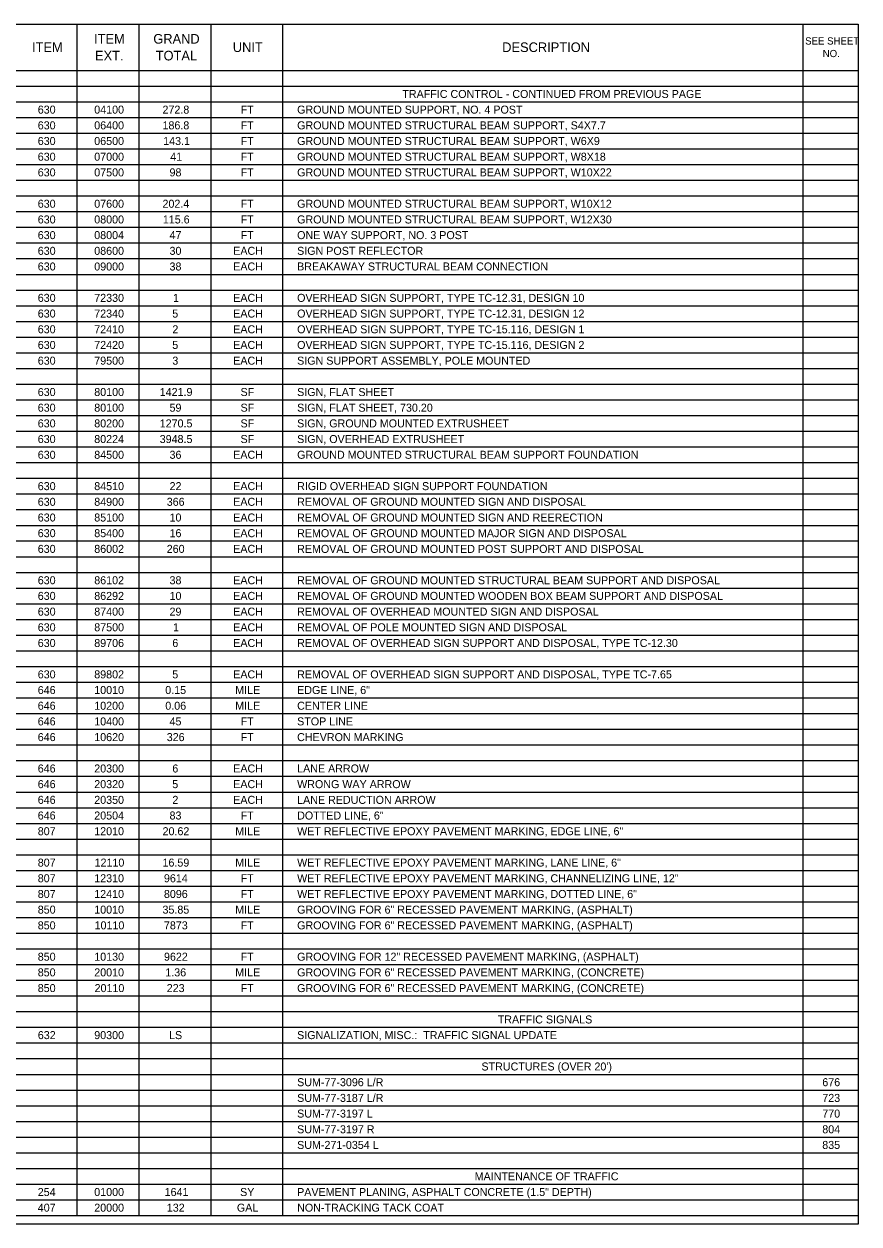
# Model space of a CAD drawing. Extents: x -542 to 295, y -281 to 32.
# Drawn here: x -400.45 to -385.84, y -130.59 to -109.59 of the extents above; entities that cross this region are included whole.
import ezdxf

# ---------------------------------------------------------------- set-up
doc = ezdxf.new("R2010")
doc.units = 0
for name, color, linetype in [('SC_Scratch1', 7, 'Continuous'), ('SH_Data', 7, 'Continuous'), ('SH_Text', 7, 'Continuous')]:
    doc.layers.add(name, color=color, linetype=linetype)

msp = doc.modelspace()

# ---------------------------------------------------------------- linework, layer by layer
at = {"layer": 'SC_Scratch1'}
msp.add_lwpolyline([(-416.359, -109.593), (-385.859, -109.593), (-385.859, -130.593), (-416.359, -130.593)], close=True, dxfattribs=at)
at = {"layer": 'SH_Data'}
for p, q in [((-416.359, -109.593), (-385.859, -109.593)), ((-399.523, -109.593), (-399.523, -130.444)), ((-398.437, -109.593), (-398.437, -130.444)), ((-397.182, -109.593), (-397.182, -130.444)), ((-395.926, -109.593), (-395.926, -130.444)), ((-386.827, -109.593), (-386.827, -130.444)), ((-385.859, -109.593), (-385.859, -130.444)), ((-416.359, -110.405), (-385.859, -110.405)), ((-416.359, -110.68), (-385.859, -110.68)), ((-416.359, -110.68), (-385.859, -110.68)), ((-416.359, -110.954), (-385.859, -110.954)), ((-416.359, -111.229), (-385.859, -111.229)), ((-416.359, -111.503), (-385.859, -111.503)), ((-416.359, -111.778), (-385.859, -111.778)), ((-416.359, -112.052), (-385.859, -112.052)), ((-416.359, -112.327), (-385.859, -112.327)), ((-416.359, -112.601), (-385.859, -112.601)), ((-416.359, -112.876), (-385.859, -112.876)), ((-416.359, -113.15), (-385.859, -113.15)), ((-416.359, -113.425), (-385.859, -113.425)), ((-416.359, -113.699), (-385.859, -113.699)), ((-416.359, -113.974), (-385.859, -113.974)), ((-416.359, -114.248), (-385.859, -114.248)), ((-416.359, -114.523), (-385.859, -114.523)), ((-416.359, -114.797), (-385.859, -114.797)), ((-416.359, -115.072), (-385.859, -115.072)), ((-416.359, -115.346), (-385.859, -115.346)), ((-416.359, -115.621), (-385.859, -115.621)), ((-416.359, -115.895), (-385.859, -115.895)), ((-416.359, -116.17), (-385.859, -116.17)), ((-416.359, -116.444), (-385.859, -116.444)), ((-416.359, -116.719), (-385.859, -116.719)), ((-416.359, -116.993), (-385.859, -116.993)), ((-416.359, -117.268), (-385.859, -117.268)), ((-416.359, -117.542), (-385.859, -117.542)), ((-416.359, -117.817), (-385.859, -117.817)), ((-416.359, -118.091), (-385.859, -118.091)), ((-416.359, -118.366), (-385.859, -118.366)), ((-416.359, -118.64), (-385.859, -118.64)), ((-416.359, -118.915), (-385.859, -118.915)), ((-416.359, -119.189), (-385.859, -119.189)), ((-416.359, -119.464), (-385.859, -119.464)), ((-416.359, -119.738), (-385.859, -119.738)), ((-416.359, -120.013), (-385.859, -120.013)), ((-416.359, -120.287), (-385.859, -120.287)), ((-416.359, -120.562), (-385.859, -120.562)), ((-416.359, -120.836), (-385.859, -120.836)), ((-416.359, -121.111), (-385.859, -121.111)), ((-416.359, -121.385), (-385.859, -121.385)), ((-416.359, -121.66), (-385.859, -121.66)), ((-416.359, -121.935), (-385.859, -121.935)), ((-416.359, -122.209), (-385.859, -122.209)), ((-416.359, -122.484), (-385.859, -122.484)), ((-416.359, -122.758), (-385.859, -122.758)), ((-416.359, -123.033), (-385.859, -123.033)), ((-416.359, -123.307), (-385.859, -123.307)), ((-416.359, -123.582), (-385.859, -123.582)), ((-416.359, -123.856), (-385.859, -123.856)), ((-416.359, -124.131), (-385.859, -124.131)), ((-416.359, -124.405), (-385.859, -124.405)), ((-416.359, -124.68), (-385.859, -124.68)), ((-416.359, -124.954), (-385.859, -124.954)), ((-416.359, -125.229), (-385.859, -125.229)), ((-416.359, -125.229), (-385.859, -125.229)), ((-416.359, -125.503), (-385.859, -125.503)), ((-416.359, -125.778), (-385.859, -125.778)), ((-416.359, -126.052), (-385.859, -126.052)), ((-416.359, -126.327), (-385.859, -126.327)), ((-416.359, -126.601), (-385.859, -126.601)), ((-416.359, -126.876), (-385.859, -126.876)), ((-416.359, -127.15), (-385.859, -127.15)), ((-416.359, -127.425), (-385.859, -127.425)), ((-416.359, -127.699), (-385.859, -127.699)), ((-416.359, -127.974), (-385.859, -127.974)), ((-416.359, -128.248), (-385.859, -128.248)), ((-416.359, -128.523), (-385.859, -128.523)), ((-416.359, -128.797), (-385.859, -128.797)), ((-416.359, -129.072), (-385.859, -129.072)), ((-416.359, -129.346), (-385.859, -129.346)), ((-416.359, -129.346), (-385.859, -129.346)), ((-416.359, -129.621), (-385.859, -129.621)), ((-416.359, -129.895), (-385.859, -129.895)), ((-416.359, -130.17), (-385.859, -130.17)), ((-416.359, -130.444), (-385.859, -130.444)), ((-416.357, -130.444), (-385.857, -130.444))]:
    msp.add_line(p, q, dxfattribs=at)

# ---------------------------------------------------------------- texts
at = {"layer": 'SH_Text'}
for s, height, p in [('ITEM', 0.168, (-399.222, -109.936)), ('GRAND ', 0.168, (-398.186, -109.936)), ('SEE SHEET ', 0.126, (-386.784, -109.952)), ('ITEM', 0.168, (-400.307, -110.083)), ('UNIT', 0.168, (-396.795, -110.083)), ('DESCRIPTION', 0.168, (-392.083, -110.083)), ('EXT.', 0.168, (-399.205, -110.23)), ('TOTAL', 0.168, (-398.144, -110.23)), ('NO.', 0.126, (-386.477, -110.172)), ('TRAFFIC CONTROL - CONTINUED FROM PREVIOUS PAGE', 0.14, (-393.83, -110.887)), ('630', 0.14, (-400.207, -111.161)), ('04100', 0.14, (-399.219, -111.161)), ('272.8', 0.14, (-398.025, -111.161)), ('FT', 0.14, (-396.658, -111.161)), ('GROUND MOUNTED SUPPORT, NO. 4 POST', 0.14, (-395.67, -111.161)), ('630', 0.14, (-400.207, -111.436)), ('06400', 0.14, (-399.219, -111.436)), ('186.8', 0.14, (-398.025, -111.436)), ('FT', 0.14, (-396.658, -111.436)), ('GROUND MOUNTED STRUCTURAL BEAM SUPPORT, S4X7.7', 0.14, (-395.67, -111.436)), ('630', 0.14, (-400.207, -111.71)), ('06500', 0.14, (-399.219, -111.71)), ('143.1', 0.14, (-398.013, -111.71)), ('FT', 0.14, (-396.658, -111.71)), ('GROUND MOUNTED STRUCTURAL BEAM SUPPORT, W6X9', 0.14, (-395.67, -111.71)), ('630', 0.14, (-400.207, -111.985)), ('07000', 0.14, (-399.219, -111.985)), ('41', 0.14, (-397.89, -111.985)), ('FT', 0.14, (-396.658, -111.985)), ('GROUND MOUNTED STRUCTURAL BEAM SUPPORT, W8X18', 0.14, (-395.67, -111.985)), ('630', 0.14, (-400.207, -112.259)), ('07500', 0.14, (-399.219, -112.259)), ('98', 0.14, (-397.902, -112.259)), ('FT', 0.14, (-396.658, -112.259)), ('GROUND MOUNTED STRUCTURAL BEAM SUPPORT, W10X22', 0.14, (-395.67, -112.259)), ('630', 0.14, (-400.207, -112.808)), ('07600', 0.14, (-399.219, -112.808)), ('202.4', 0.14, (-398.025, -112.808)), ('FT', 0.14, (-396.658, -112.808)), ('GROUND MOUNTED STRUCTURAL BEAM SUPPORT, W10X12', 0.14, (-395.67, -112.808)), ('630', 0.14, (-400.207, -113.083)), ('08000', 0.14, (-399.219, -113.083)), ('115.6', 0.14, (-398.019, -113.083)), ('FT', 0.14, (-396.658, -113.083)), ('GROUND MOUNTED STRUCTURAL BEAM SUPPORT, W12X30', 0.14, (-395.67, -113.083)), ('630', 0.14, (-400.207, -113.357)), ('08004', 0.14, (-399.219, -113.357)), ('47', 0.14, (-397.902, -113.357)), ('FT', 0.14, (-396.658, -113.357)), ('ONE WAY SUPPORT, NO. 3 POST', 0.14, (-395.67, -113.357)), ('630', 0.14, (-400.207, -113.632)), ('08600', 0.14, (-399.219, -113.632)), ('30', 0.14, (-397.902, -113.632)), ('EACH', 0.14, (-396.788, -113.632)), ('SIGN POST REFLECTOR', 0.14, (-395.67, -113.632)), ('630', 0.14, (-400.207, -113.906)), ('09000', 0.14, (-399.219, -113.906)), ('38', 0.14, (-397.902, -113.906)), ('EACH', 0.14, (-396.788, -113.906)), ('BREAKAWAY STRUCTURAL BEAM CONNECTION', 0.14, (-395.67, -113.906)), ('630', 0.14, (-400.207, -114.455)), ('72330', 0.14, (-399.219, -114.455)), ('1', 0.14, (-397.841, -114.455)), ('EACH', 0.14, (-396.788, -114.455)), ('OVERHEAD SIGN SUPPORT, TYPE TC-12.31, DESIGN 10', 0.14, (-395.67, -114.455)), ('630', 0.14, (-400.207, -114.73)), ('72340', 0.14, (-399.219, -114.73)), ('5', 0.14, (-397.854, -114.73)), ('EACH', 0.14, (-396.788, -114.73)), ('OVERHEAD SIGN SUPPORT, TYPE TC-12.31, DESIGN 12', 0.14, (-395.67, -114.73)), ('630', 0.14, (-400.207, -115.005)), ('72410', 0.14, (-399.219, -115.005)), ('2', 0.14, (-397.852, -115.005)), ('EACH', 0.14, (-396.788, -115.005)), ('OVERHEAD SIGN SUPPORT, TYPE TC-15.116, DESIGN 1', 0.14, (-395.67, -115.005)), ('630', 0.14, (-400.207, -115.279)), ('72420', 0.14, (-399.219, -115.279)), ('5', 0.14, (-397.854, -115.279)), ('EACH', 0.14, (-396.788, -115.279)), ('OVERHEAD SIGN SUPPORT, TYPE TC-15.116, DESIGN 2', 0.14, (-395.67, -115.279)), ('630', 0.14, (-400.207, -115.554)), ('79500', 0.14, (-399.219, -115.554)), ('3', 0.14, (-397.853, -115.554)), ('EACH', 0.14, (-396.788, -115.554)), ('SIGN SUPPORT ASSEMBLY, POLE MOUNTED', 0.14, (-395.67, -115.554)), ('630', 0.14, (-400.207, -116.103)), ('80100', 0.14, (-399.219, -116.103)), ('1421.9', 0.14, (-398.074, -116.103)), ('SF', 0.14, (-396.66, -116.103)), ('SIGN, FLAT SHEET', 0.14, (-395.67, -116.103)), ('630', 0.14, (-400.207, -116.377)), ('80100', 0.14, (-399.219, -116.377)), ('59', 0.14, (-397.902, -116.377)), ('SF', 0.14, (-396.66, -116.377)), ('SIGN, FLAT SHEET, 730.20', 0.14, (-395.67, -116.377)), ('630', 0.14, (-400.207, -116.652)), ('80200', 0.14, (-399.219, -116.652)), ('1270.5', 0.14, (-398.074, -116.652)), ('SF', 0.14, (-396.66, -116.652)), ('SIGN, GROUND MOUNTED EXTRUSHEET', 0.14, (-395.67, -116.652)), ('630', 0.14, (-400.207, -116.926)), ('80224', 0.14, (-399.219, -116.926)), ('3948.5', 0.14, (-398.074, -116.926)), ('SF', 0.14, (-396.66, -116.926)), ('SIGN, OVERHEAD EXTRUSHEET', 0.14, (-395.67, -116.926)), ('630', 0.14, (-400.207, -117.201)), ('84500', 0.14, (-399.219, -117.201)), ('36', 0.14, (-397.902, -117.201)), ('EACH', 0.14, (-396.788, -117.201)), ('GROUND MOUNTED STRUCTURAL BEAM SUPPORT FOUNDATION', 0.14, (-395.67, -117.201)), ('630', 0.14, (-400.207, -117.75)), ('84510', 0.14, (-399.219, -117.75)), ('22', 0.14, (-397.901, -117.75)), ('EACH', 0.14, (-396.788, -117.75)), ('RIGID OVERHEAD SIGN SUPPORT FOUNDATION', 0.14, (-395.67, -117.75)), ('630', 0.14, (-400.207, -118.024)), ('84900', 0.14, (-399.219, -118.024)), ('366', 0.14, (-397.951, -118.024)), ('EACH', 0.14, (-396.788, -118.024)), ('REMOVAL OF GROUND MOUNTED SIGN AND DISPOSAL', 0.14, (-395.67, -118.024)), ('630', 0.14, (-400.207, -118.299)), ('85100', 0.14, (-399.219, -118.299)), ('10', 0.14, (-397.902, -118.299)), ('EACH', 0.14, (-396.788, -118.299)), ('REMOVAL OF GROUND MOUNTED SIGN AND REERECTION', 0.14, (-395.67, -118.299)), ('630', 0.14, (-400.207, -118.573)), ('85400', 0.14, (-399.219, -118.573)), ('16', 0.14, (-397.902, -118.573)), ('EACH', 0.14, (-396.788, -118.573)), ('REMOVAL OF GROUND MOUNTED MAJOR SIGN AND DISPOSAL', 0.14, (-395.67, -118.573)), ('630', 0.14, (-400.207, -118.848)), ('86002', 0.14, (-399.219, -118.848)), ('260', 0.14, (-397.951, -118.848)), ('EACH', 0.14, (-396.788, -118.848)), ('REMOVAL OF GROUND MOUNTED POST SUPPORT AND DISPOSAL', 0.14, (-395.67, -118.848)), ('630', 0.14, (-400.207, -119.397)), ('86102', 0.14, (-399.219, -119.397)), ('38', 0.14, (-397.902, -119.397)), ('EACH', 0.14, (-396.788, -119.397)), ('REMOVAL OF GROUND MOUNTED STRUCTURAL BEAM SUPPORT AND DISPOSAL', 0.14, (-395.67, -119.397)), ('630', 0.14, (-400.207, -119.671)), ('86292', 0.14, (-399.219, -119.671)), ('10', 0.14, (-397.902, -119.671)), ('EACH', 0.14, (-396.788, -119.671)), ('REMOVAL OF GROUND MOUNTED WOODEN BOX BEAM SUPPORT AND DISPOSAL', 0.14, (-395.67, -119.671)), ('630', 0.14, (-400.207, -119.946)), ('87400', 0.14, (-399.219, -119.946)), ('29', 0.14, (-397.902, -119.946)), ('EACH', 0.14, (-396.788, -119.946)), ('REMOVAL OF OVERHEAD MOUNTED SIGN AND DISPOSAL', 0.14, (-395.67, -119.946)), ('630', 0.14, (-400.207, -120.22)), ('87500', 0.14, (-399.219, -120.22)), ('1', 0.14, (-397.841, -120.22)), ('EACH', 0.14, (-396.788, -120.22)), ('REMOVAL OF POLE MOUNTED SIGN AND DISPOSAL', 0.14, (-395.67, -120.22)), ('630', 0.14, (-400.207, -120.495)), ('89706', 0.14, (-399.219, -120.495)), ('6', 0.14, (-397.853, -120.495)), ('EACH', 0.14, (-396.788, -120.495)), ('REMOVAL OF OVERHEAD SIGN SUPPORT AND DISPOSAL, TYPE TC-12.30', 0.14, (-395.67, -120.495)), ('630', 0.14, (-400.207, -121.044)), ('89802', 0.14, (-399.219, -121.044)), ('5', 0.14, (-397.854, -121.044)), ('EACH', 0.14, (-396.788, -121.044)), ('REMOVAL OF OVERHEAD SIGN SUPPORT AND DISPOSAL, TYPE TC-7.65', 0.14, (-395.67, -121.044)), ('646', 0.14, (-400.207, -121.318)), ('10010', 0.14, (-399.219, -121.318)), ('0.15', 0.14, (-397.977, -121.318)), ('MILE', 0.14, (-396.753, -121.318)), ('EDGE LINE, 6"', 0.14, (-395.67, -121.318)), ('646', 0.14, (-400.207, -121.593)), ('10200', 0.14, (-399.219, -121.593)), ('0.06', 0.14, (-397.976, -121.593)), ('MILE', 0.14, (-396.753, -121.593)), ('CENTER LINE', 0.14, (-395.67, -121.593)), ('646', 0.14, (-400.207, -121.867)), ('10400', 0.14, (-399.219, -121.867)), ('45', 0.14, (-397.902, -121.867)), ('FT', 0.14, (-396.658, -121.867)), ('STOP LINE', 0.14, (-395.67, -121.867)), ('646', 0.14, (-400.207, -122.142)), ('10620', 0.14, (-399.219, -122.142)), ('326', 0.14, (-397.951, -122.142)), ('FT', 0.14, (-396.658, -122.142)), ('CHEVRON MARKING', 0.14, (-395.67, -122.142)), ('646', 0.14, (-400.207, -122.691)), ('20300', 0.14, (-399.219, -122.691)), ('6', 0.14, (-397.853, -122.691)), ('EACH', 0.14, (-396.788, -122.691)), ('LANE ARROW', 0.14, (-395.67, -122.691)), ('646', 0.14, (-400.207, -122.965)), ('20320', 0.14, (-399.219, -122.965)), ('5', 0.14, (-397.854, -122.965)), ('EACH', 0.14, (-396.788, -122.965)), ('WRONG WAY ARROW', 0.14, (-395.67, -122.965)), ('646', 0.14, (-400.207, -123.24)), ('20350', 0.14, (-399.219, -123.24)), ('2', 0.14, (-397.852, -123.24)), ('EACH', 0.14, (-396.788, -123.24)), ('LANE REDUCTION ARROW', 0.14, (-395.67, -123.24)), ('646', 0.14, (-400.207, -123.514)), ('20504', 0.14, (-399.219, -123.514)), ('83', 0.14, (-397.902, -123.514)), ('FT', 0.14, (-396.658, -123.514)), ('DOTTED LINE, 6"', 0.14, (-395.67, -123.514)), ('807', 0.14, (-400.207, -123.789)), ('12010', 0.14, (-399.219, -123.789)), ('20.62', 0.14, (-398.024, -123.789)), ('MILE', 0.14, (-396.753, -123.789)), ('WET REFLECTIVE EPOXY PAVEMENT MARKING, EDGE LINE, 6"', 0.14, (-395.67, -123.789)), ('807', 0.14, (-400.207, -124.338)), ('12110', 0.14, (-399.213, -124.338)), ('16.59', 0.14, (-398.025, -124.338)), ('MILE', 0.14, (-396.753, -124.338)), ('WET REFLECTIVE EPOXY PAVEMENT MARKING, LANE LINE, 6"', 0.14, (-395.67, -124.338)), ('807', 0.14, (-400.207, -124.612)), ('12310', 0.14, (-399.219, -124.612)), ('9614', 0.14, (-398, -124.612)), ('FT', 0.14, (-396.658, -124.612)), ('WET REFLECTIVE EPOXY PAVEMENT MARKING, CHANNELIZING LINE, 12"', 0.14, (-395.67, -124.612)), ('807', 0.14, (-400.207, -124.887)), ('12410', 0.14, (-399.219, -124.887)), ('8096', 0.14, (-398, -124.887)), ('FT', 0.14, (-396.658, -124.887)), ('WET REFLECTIVE EPOXY PAVEMENT MARKING, DOTTED LINE, 6"', 0.14, (-395.67, -124.887)), ('850', 0.14, (-400.207, -125.161)), ('10010', 0.14, (-399.219, -125.161)), ('35.85', 0.14, (-398.025, -125.161)), ('MILE', 0.14, (-396.753, -125.161)), ('GROOVING FOR 6" RECESSED PAVEMENT MARKING, (ASPHALT)', 0.14, (-395.67, -125.161)), ('850', 0.14, (-400.207, -125.436)), ('10110', 0.14, (-399.213, -125.436)), ('7873', 0.14, (-398, -125.436)), ('FT', 0.14, (-396.658, -125.436)), ('GROOVING FOR 6" RECESSED PAVEMENT MARKING, (ASPHALT)', 0.14, (-395.67, -125.436)), ('850', 0.14, (-400.207, -125.985)), ('10130', 0.14, (-399.219, -125.985)), ('9622', 0.14, (-397.999, -125.985)), ('FT', 0.14, (-396.658, -125.985)), ('GROOVING FOR 12" RECESSED PAVEMENT MARKING, (ASPHALT)', 0.14, (-395.67, -125.985)), ('850', 0.14, (-400.207, -126.259)), ('20010', 0.14, (-399.219, -126.259)), ('1.36', 0.14, (-397.976, -126.259)), ('MILE', 0.14, (-396.753, -126.259)), ('GROOVING FOR 6" RECESSED PAVEMENT MARKING, (CONCRETE)', 0.14, (-395.67, -126.259)), ('850', 0.14, (-400.207, -126.534)), ('20110', 0.14, (-399.213, -126.534)), ('223', 0.14, (-397.951, -126.534)), ('FT', 0.14, (-396.658, -126.534)), ('GROOVING FOR 6" RECESSED PAVEMENT MARKING, (CONCRETE)', 0.14, (-395.67, -126.534)), ('TRAFFIC SIGNALS', 0.14, (-392.161, -127.083)), ('632', 0.14, (-400.206, -127.357)), ('90300', 0.14, (-399.219, -127.357)), ('LS', 0.14, (-397.911, -127.357)), ('SIGNALIZATION, MISC.:  TRAFFIC SIGNAL UPDATE', 0.14, (-395.67, -127.357)), ("STRUCTURES (OVER 20')", 0.14, (-392.446, -127.906)), ('SUM-77-3096 L/R', 0.14, (-395.67, -128.181)), ('676', 0.14, (-386.484, -128.181)), ('SUM-77-3187 L/R', 0.14, (-395.67, -128.456)), ('723', 0.14, (-386.484, -128.456)), ('SUM-77-3197 L', 0.14, (-395.67, -128.73)), ('770', 0.14, (-386.484, -128.73)), ('SUM-77-3197 R', 0.14, (-395.67, -129.005)), ('804', 0.14, (-386.484, -129.005)), ('SUM-271-0354 L', 0.14, (-395.67, -129.279)), ('835', 0.14, (-386.485, -129.279)), ('MAINTENANCE OF TRAFFIC', 0.14, (-392.565, -129.828)), ('254', 0.14, (-400.207, -130.103)), ('01000', 0.14, (-399.219, -130.103)), ('1641', 0.14, (-397.988, -130.103)), ('SY', 0.14, (-396.668, -130.103)), ('PAVEMENT PLANING, ASPHALT CONCRETE (1.5" DEPTH)', 0.14, (-395.67, -130.103)), ('407', 0.14, (-400.207, -130.377)), ('20000', 0.14, (-399.219, -130.377)), ('132', 0.14, (-397.95, -130.377)), ('GAL', 0.14, (-396.724, -130.377)), ('NON-TRACKING TACK COAT', 0.14, (-395.67, -130.377))]:
    msp.add_text(s, height=height, dxfattribs=at).set_placement(p)

doc.saveas('drawing.dxf')
